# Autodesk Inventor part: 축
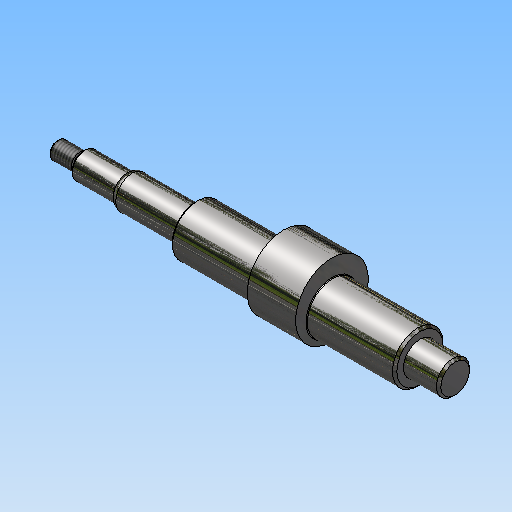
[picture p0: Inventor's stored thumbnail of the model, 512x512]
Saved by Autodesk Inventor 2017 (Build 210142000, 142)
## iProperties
Created: 2015-12
Part Number: 축
Document SubType Name: Modeling
Designer: mdu
Density: 7.86 g/cm^3
Material: 강철, 연강
Mass: 494.666 g
Surface Area: 129.298 cm^2
Volume: 62.9347 cm^3
Appearance: 반광택
Author: mdu
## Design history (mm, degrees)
sketch "스케치1"
  geometry: L1 (62, 100.9)-(62, 67.1) reference; L2 (51, 101.2)-(51, 84) reference; L3 (-51, 84)-(-51, 101.2) reference; L4 (-62, 67.1)-(-62, 100.9) reference; L5 (-51.6, 91.5)-(-61.4, 91.5) reference; L6 (51.6, 91.5)-(61.4, 91.5) reference; L7 (67, 84)-(-114, 84); L8 (-77, 64.201)-(-77, 103.799) reference; L9 (67, 84)-(67, 91.5); L10 (67, 91.5)-(51, 91.5); L11 (51, 91.5)-(51, 95.5); L12 (51, 95.5)-(-51, 95.5); L13 (-51, 95.5)-(-51, 91.5); L14 (-51, 91.5)-(-82, 91.5); L15 (-82, 91.5)-(-82, 90); L16 (-82, 90)-(-102, 90); L17 (-102, 90)-(-102, 87); L18 (-103.5, 88)-(-114, 88); L19 (-114, 88)-(-114, 84); L20 (-102, 87)-(-103.5, 87); L21 (-103.5, 87)-(-103.5, 88); 2 further points
  constraints: 32 end point, 7 parallel, 6 point on line, 5 perpendicular, 2 collinear, 2 horizontal, 1 midpoint, 4 other
  dimensions: "d0" = 5 distance from line of L7.start L1; "d2" = 5 distance between parallel lines of L15 L8; "d3" = 23 diameter of L12 L7; "d4" = 12 diameter of L16 L7; "d5" = 1.5 distance of L17.end L20.end; "d6" = 6 diameter of L20 L7; "d7" = 20 distance of L15.end L16.end; "d8" = 12 distance between parallel lines of L17 L19; "d9" = 8 diameter of L18 L7
revolve "회전1" sketch "스케치1" stored, may be unused: angle "d10" = 90 deg
sketch "스케치2"
  geometry: C1 r 11.5 at (84, 0) reference; C2 r 11.5 at (84, 0) reference; C3 r 16.5 at (87, 0); 1 further point
  constraints: 1 centre point, 1 horizontal alignment
  dimensions: "d11" = 33 diameter of C3; "d12" = 3 distance of C3.centre C1.centre
extrude "돌출1" join sketch "스케치2" stored distance "d13" = 22; taper "d14" = 0 deg
chamfer "모따기1" distance "d15" = 1; stored, may be unused: second distance "d16" = 2, angle "d17" = 45 deg
feature "스레드1" dims "d18" = 10, "d19" = 0
node "작업 평면1"
sketch "스케치3"
  geometry: L1 (-5, -2)-(3, -2); L2 (3, 2)-(-5, 2); L3 (-10, -5)-(-10, 5) reference; A1 r 2 centre (3, 0) between (3, -2) and (3, 2); A2 r 2 centre (-5, 0) between (-5, 2) and (-5, -2); 2 further points
  constraints: 4 end point, 4 point on circle, 4 tangent, 2 centre point, 1 horizontal, 1 horizontal alignment, 1 midpoint, 1 parallel
  dimensions: "d20" = 4 distance between parallel lines of L1 L2; "d21" = 12 dimension on A1 A2; "d22" = 3 distance edge to line of A2 L3
extrude "돌출2" cut sketch "스케치3" distance "d23" = 2.5; taper "d24" = 0 deg
fillet "모깎기1" dims "d25" = 0.3
fillet "모깎기2" dims "d26" = 3
node "솔리드1"
node "참조1"
node "참조2"
node "참조3"
node "참조4"
node "참조5"
node "투영된 루프1"
